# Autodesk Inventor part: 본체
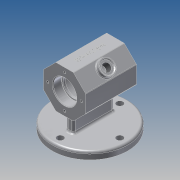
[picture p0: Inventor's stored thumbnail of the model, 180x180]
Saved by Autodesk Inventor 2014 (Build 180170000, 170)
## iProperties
Created: 2021-02
Part Number: 본체
Material: 알루미늄 6061
Document SubType Name: Modeling
Designer: kb542-17
Density: 2.71 g/cm^3
Appearance: 알루미늄 - 평지
Mass: 558.806 g
Surface Area: 509.67 cm^2
Volume: 206.202 cm^3
Author: kb542-17
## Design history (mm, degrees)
sketch "스케치1"
  geometry: C1 r 52 at (0, 0); C2 r 4.5 at (41, 0); C3 r 4.5 at (0, 41); C4 r 4.5 at (-41, 0); C5 r 4.5 at (0, -41); A1 r 41 centre (0, 0) between (41, 0) and (0, 41); 1 further point
  constraints: 6 centre point, 4 point on circle, 3 equal radius, 2 coincident, 2 horizontal alignment, 2 vertical alignment
  dimensions: "d0" = 104 diameter of C1; "d1" = 82 diameter of A1; "d2" = 9 diameter of C2
extrude "돌출1" new body sketch "스케치1" distance "d3" = 10; taper "d4" = 0 deg
sketch "스케치2" dims "d44" = 58
  geometry: L1 (12.012, 91)-(29, 74.012); L2 (29, 74.012)-(29, 49.988); L3 (29, 49.988)-(12.012, 33); L4 (12.012, 33)-(-12.012, 33); L5 (-12.012, 33)-(-29, 49.988); L6 (-29, 49.988)-(-29, 74.012); L7 (-29, 74.012)-(-12.012, 91); L8 (-12.012, 91)-(12.012, 91); 4 further points
  constraints: 16 end point, 2 vertical alignment, 1 coincident, 1 horizontal, 1 midpoint, 19 other
  dimensions: "d45" = 62 distance of point (0, 62) point (0, 0)
extrude "돌출2" join sketch "스케치2" stored distance "d7" = 70; taper "d8" = 0 deg
sketch "스케치7"
  geometry: L1 (-35, 74.012)-(-35, 49.988) reference; L2 (35, 49.988)-(35, 74.012) reference; L3 (-35, 62)-(35, 62); L4 (-35, 62)-(-35, 78); L5 (-35, 78)-(-23, 78); L6 (-23, 78)-(-23, 76); L7 (-23, 76)-(-20, 76); L8 (-20, 76)-(-20, 84); L9 (-20, 84)-(20, 84); L10 (20, 84)-(20, 76); L11 (20, 76)-(23, 76); L12 (23, 76)-(23, 78); L13 (23, 78)-(35, 78); L14 (35, 78)-(35, 62); 1 further point
  constraints: 24 end point, 6 perpendicular, 4 parallel, 2 midpoint, 1 collinear, 1 horizontal
  dimensions: "d55" = 44 diameter of L9 L3; "d56" = 28 diameter of L11 L3; "d57" = 32 diameter of L13 L3; "d58" = 28 diameter of L7 L3; "d59" = 32 diameter of L5 L3; "d60" = 12 distance of L4.end L5.end; "d61" = 3 distance of L6.end L7.end; "d62" = 40 distance of L8.end L9.end; "d63" = 12 distance of L12.end L13.end
revolve "회전2" sketch "스케치7" stored, may be unused: angle "d64" = 90 deg
sketch "스케치8"
  geometry: L1 (-5, -28)-(5, -28); L2 (5, -28)-(5, 28); L3 (5, 28)-(-5, 28); L4 (-5, 28)-(-5, -28); C1 r 52 at (0, 0) reference; 2 further points
  constraints: 8 end point, 2 midpoint, 2 parallel, 1 horizontal, 1 horizontal alignment, 1 perpendicular, 1 vertical alignment
  dimensions: "d65" = 10 distance between parallel lines of L2 L4; "d66" = 56 distance between parallel lines of L1 L3
extrude "돌출5" join sketch "스케치8" stored distance "d67" = 5; taper "d68" = 0 deg
sketch "스케치9"
  geometry: L1 (0, 0)-(-24.024, 0) reference; C1 r 10 at (-12.012, 35); 2 further points
  constraints: 1 centre point, 1 midpoint, 1 vertical alignment
  dimensions: "d69" = 20 diameter of C1; "d70" = 35 distance from line of L1 C1.centre
extrude "돌출6" join sketch "스케치9" distance "d71" = 5; taper "d72" = 0 deg
hole "구멍3" diameter "d75" = 10.917; stored, may be unused: countersink angle "d79" = 90 deg, drill point angle "d81" = 118 deg; dims "d73" = 10, "d74" = 10, "d76" = 8, "d77" = 16, "d78" = 2, "d80" = 10
sketch "스케치10" dims "d82" = 46
  geometry: C1 r 16 at (0, 62) reference; 3 further points
  constraints: 2 vertical alignment, 1 coincident, 2 other
hole "구멍4" sketch "스케치10" at (0, 85) diameter "d83" = 3.242; stored, may be unused: countersink angle "d87" = 90 deg, drill point angle "d89" = 118 deg; dims "d84" = 8, "d85" = 16, "d86" = 2, "d88" = 10
node "작업 평면1"
sketch "스케치11"
  geometry: L1 (24.024, -70)-(0, -70) reference; L2 (-16.988, 0)-(-16.988, -70) reference; 2 further points
  constraints: 1 other
  dimensions: "d94" = 35 distance from line of L1 point (12.012, -35); "d95" = 29 distance from line of L2 point (12.012, -35)
feature "엠보싱1" sketch "스케치11" dims "d96" = 0.5, "d97" = 0
fillet "모깎기1" dims "d98" = 1, "d99" = 0.3, "d100" = 3
fillet "모깎기2" dims "d101" = 3
chamfer "모따기1" distance "d102" = 1; stored, may be unused: second distance "d103" = 2, angle "d104" = 45 deg
node "솔리드1"
pattern_circular "원형 패턴1" dims angle "d91" = 360 deg
mirror "대칭1"
other parameters: "d93" = 23
